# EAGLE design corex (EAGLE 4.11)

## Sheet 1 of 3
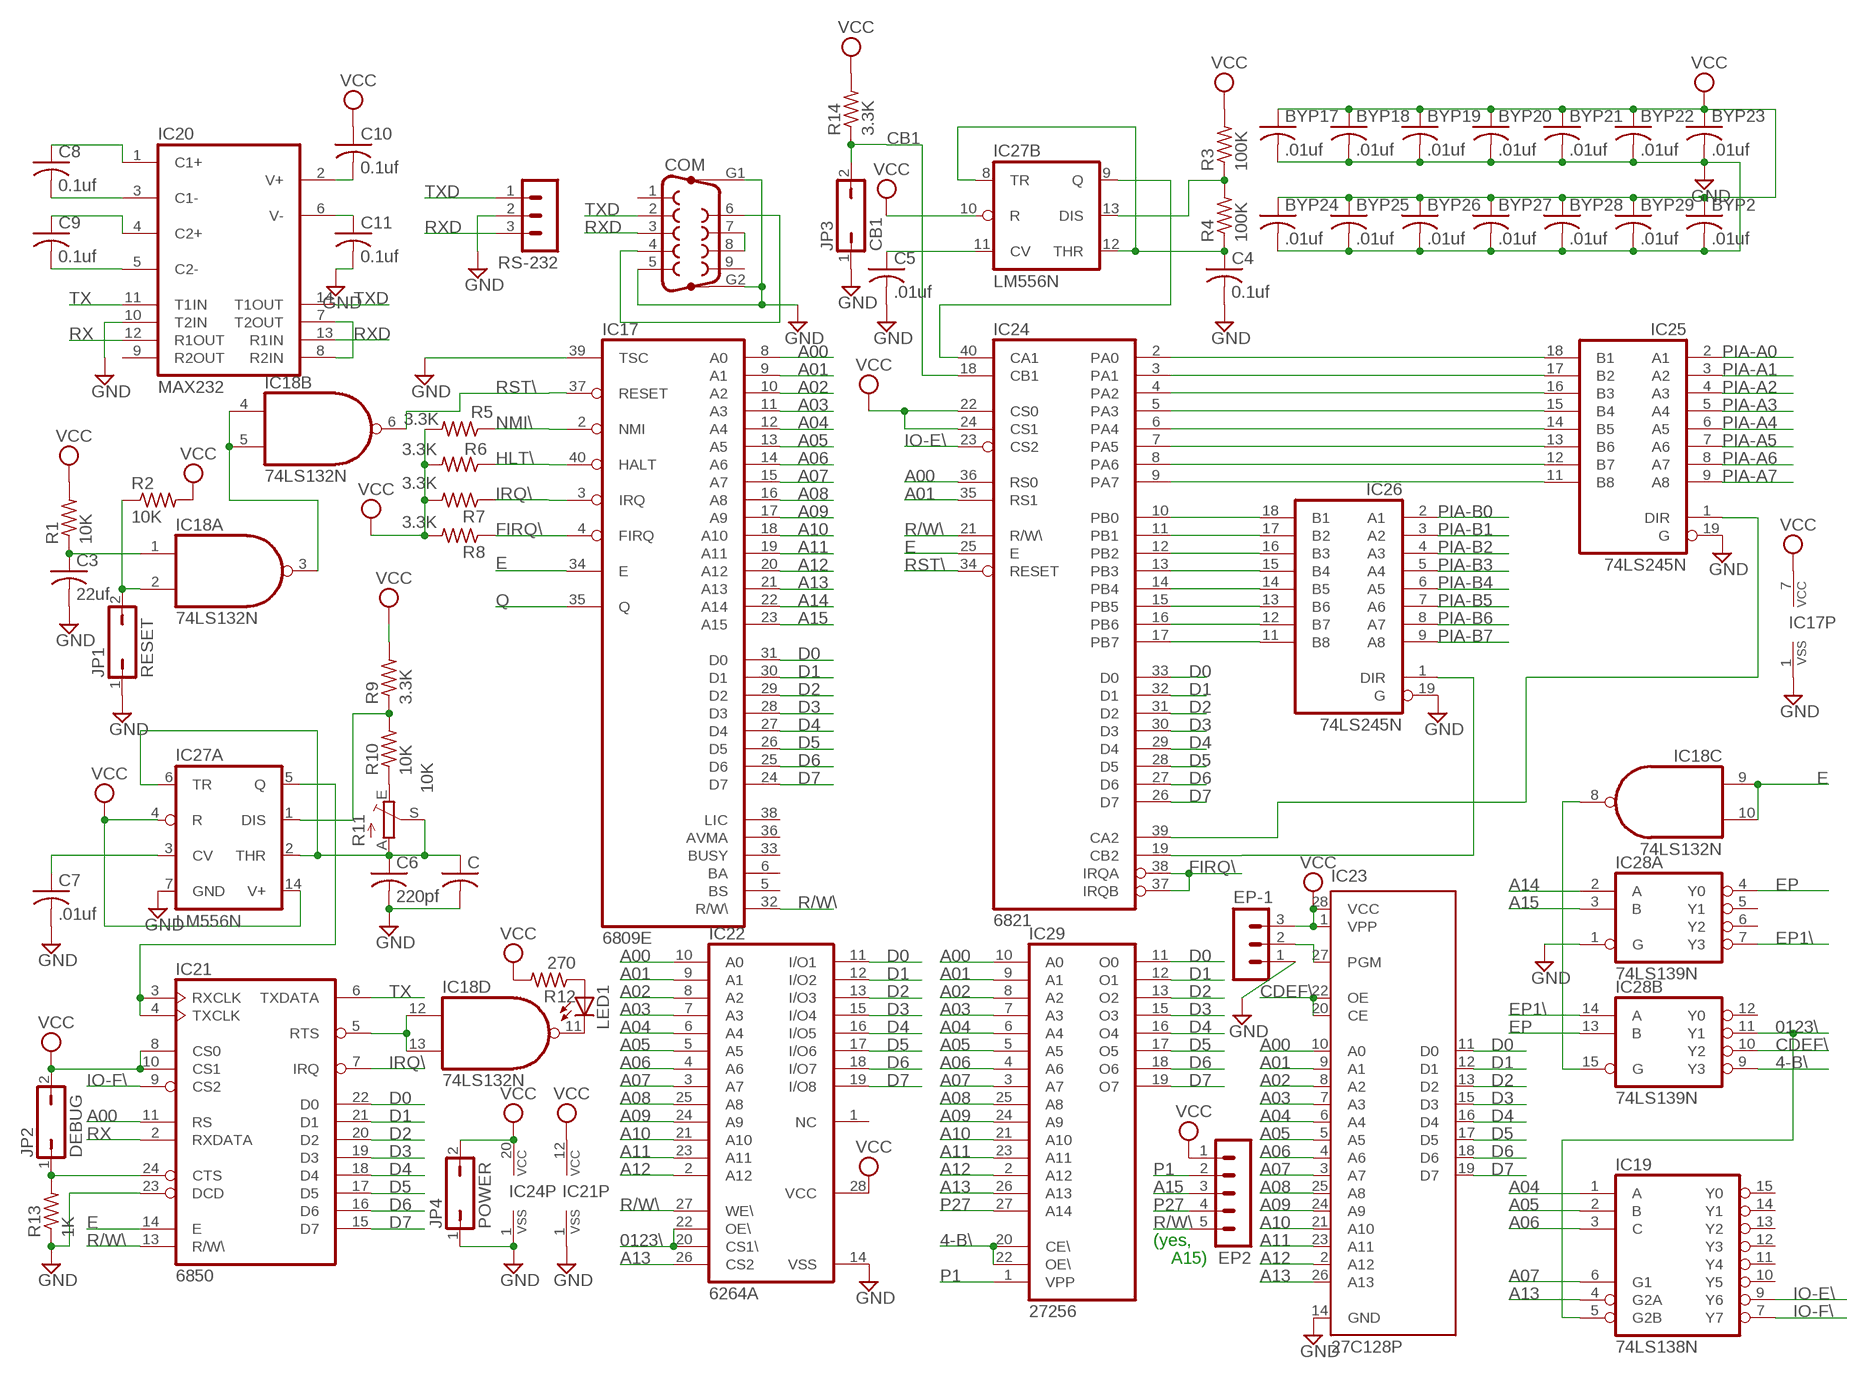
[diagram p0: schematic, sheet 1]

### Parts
BYP2  .01uf  C-US050-025X075  [C050-025X075]
BYP17  .01uf  C-US050-025X075  [C050-025X075]
BYP18  .01uf  C-US050-025X075  [C050-025X075]
BYP19  .01uf  C-US050-025X075  [C050-025X075]
BYP20  .01uf  C-US050-025X075  [C050-025X075]
BYP21  .01uf  C-US050-025X075  [C050-025X075]
BYP22  .01uf  C-US050-025X075  [C050-025X075]
BYP23  .01uf  C-US050-025X075  [C050-025X075]
BYP24  .01uf  C-US050-025X075  [C050-025X075]
BYP25  .01uf  C-US050-025X075  [C050-025X075]
BYP26  .01uf  C-US050-025X075  [C050-025X075]
BYP27  .01uf  C-US050-025X075  [C050-025X075]
BYP28  .01uf  C-US050-025X075  [C050-025X075]
BYP29  .01uf  C-US050-025X075  [C050-025X075]
C  C-US050-025X075  [C050-025X075]
C3  22uf  C-US102-054X133  [C102-054X133]
C4  0.1uf  C-US050-025X075  [C050-025X075]
C5  .01uf  C-US050-025X075  [C050-025X075]
C6  220pf  C-US050-025X075  [C050-025X075]
C7  .01uf  C-US050-025X075  [C050-025X075]
C8  0.1uf  C-US050-025X075  [C050-025X075]
C9  0.1uf  C-US050-025X075  [C050-025X075]
C10  0.1uf  C-US050-025X075  [C050-025X075]
C11  0.1uf  C-US050-025X075  [C050-025X075]
COM  F09HP  [F09HP]
EP2  MA05-1  [MA05-1]
EP-1  MA03-1  [MA03-1]
IC17  6809E  [DIL40]
IC18  74LS132N  74LS00N  [DIL14]
IC19  74LS138N  [DIL16]
IC20  MAX232  [DIL16]
IC21  6850  [DIL24]
IC22  6264A  [DIL28-6]
IC23  27C128P  [DIL28-6]
IC24  6821  [DIL40]
IC25  74LS245N  [DIL20]
IC26  74LS245N  [DIL20]
IC27  LM556N  [DIL14]
IC28  74LS139N  [DIL16]
IC29  27256  [DIL28]
JP1  RESET  JP1Q  [JP1]
JP2  DEBUG  JP1Q  [JP1]
JP3  CB1  JP1Q  [JP1]
JP4  POWER  JP1Q  [JP1]
LED1  LED3MM  [LED3MM]
R1  10K  R-US_0207/7  [0207/7]
R2  10K  R-US_0207/7  [0207/7]
R3  100K  R-US_0207/7  [0207/7]
R4  100K  R-US_0207/7  [0207/7]
R5  3.3K  R-US_0207/7  [0207/7]
R6  3.3K  R-US_0207/7  [0207/7]
R7  3.3K  R-US_0207/7  [0207/7]
R8  3.3K  R-US_0207/7  [0207/7]
R9  3.3K  R-US_0207/7  [0207/7]
R10  10K  R-US_0207/7  [0207/7]
R11  10K  TRIM_EU-B90P  [SP19L]
R12  270  R-US_0207/7  [0207/7]
R13  1K  R-US_0207/7  [0207/7]
R14  3.3K  R-US_0207/7  [0207/7]
RS-232  MA03-1  [MA03-1]

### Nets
4-B\: IC28.9(B:Y3) IC29.20(CE\) IC29.22(OE\)
0123\: IC19.5(G2B) IC22.20(CS1\) IC22.22(OE\) IC28.11(B:Y1)
A00: IC17.8(A0) IC21.11(RS) IC22.10(A0) IC23.10(A0) IC24.36(RS0) IC29.10(A0)
A01: IC17.9(A1) IC22.9(A1) IC23.9(A1) IC24.35(RS1) IC29.9(A1)
A02: IC17.10(A2) IC22.8(A2) IC23.8(A2) IC29.8(A2)
A03: IC17.11(A3) IC22.7(A3) IC23.7(A3) IC29.7(A3)
A04: IC17.12(A4) IC19.1(A) IC22.6(A4) IC23.6(A4) IC29.6(A4)
A05: IC17.13(A5) IC19.2(B) IC22.5(A5) IC23.5(A5) IC29.5(A5)
A06: IC17.14(A6) IC19.3(C) IC22.4(A6) IC23.4(A6) IC29.4(A6)
A07: IC17.15(A7) IC19.6(G1) IC22.3(A7) IC23.3(A7) IC29.3(A7)
A08: IC17.16(A8) IC22.25(A8) IC23.25(A8) IC29.25(A8)
A09: IC17.17(A9) IC22.24(A9) IC23.24(A9) IC29.24(A9)
A10: IC17.18(A10) IC22.21(A10) IC23.21(A10) IC29.21(A10)
A11: IC17.19(A11) IC22.23(A11) IC23.23(A11) IC29.23(A11)
A12: IC17.20(A12) IC22.2(A12) IC23.2(A12) IC29.2(A12)
A13: IC17.21(A13) IC19.4(G2A) IC22.26(CS2) IC23.26(A13) IC29.26(A13)
A14: IC17.22(A14) IC28.2(A:A)
A15: EP2.3 IC17.23(A15) IC28.3(A:B)
CB1: IC24.18(CB1) JP3.2 R14.1
CDEF\: IC23.20(CE) IC23.22(OE) IC28.10(B:Y2)
D0: IC17.31(D0) IC21.22(D0) IC22.11(I/O1) IC23.11(D0) IC24.33(D0) IC29.11(O0)
D1: IC17.30(D1) IC21.21(D1) IC22.12(I/O2) IC23.12(D1) IC24.32(D1) IC29.12(O1)
D2: IC17.29(D2) IC21.20(D2) IC22.13(I/O3) IC23.13(D2) IC24.31(D2) IC29.13(O2)
D3: IC17.28(D3) IC21.19(D3) IC22.15(I/O4) IC23.15(D3) IC24.30(D3) IC29.15(O3)
D4: IC17.27(D4) IC21.18(D4) IC22.16(I/O5) IC23.16(D4) IC24.29(D4) IC29.16(O4)
D5: IC17.26(D5) IC21.17(D5) IC22.17(I/O6) IC23.17(D5) IC24.28(D5) IC29.17(O5)
D6: IC17.25(D6) IC21.16(D6) IC22.18(I/O7) IC23.18(D6) IC24.27(D6) IC29.18(O6)
D7: IC17.24(D7) IC21.15(D7) IC22.19(I/O8) IC23.19(D7) IC24.26(D7) IC29.19(O7)
E: IC17.34(E) IC18.9(C:I0) IC18.10(C:I1) IC21.14(E) IC24.25(E) ; also sheet 3
EP: IC28.4(A:Y0) IC28.13(B:B)
EP1\: IC28.7(A:Y3) IC28.14(B:A)
FIRQ\: IC17.4(FIRQ) IC24.37(IRQB) IC24.38(IRQA) R8.1
GND [Power]: BYP2.2 BYP17.2 BYP18.2 BYP19.2 BYP20.2 BYP21.2 BYP22.2 BYP23.2 BYP24.2 BYP25.2 BYP26.2 BYP27.2 BYP28.2 BYP29.2 C3.2 C4.2 C5.2 C6.2 C7.2 C11.2 C.2 COM.5 COM.G1 COM.G2 EP-1.1 IC17.1(VSS) IC17.39(TSC) IC20.10(T2IN) IC21.1(VSS) IC21.23(DCD) IC22.14(VSS) IC23.14(GND) IC24.1(VSS) IC25.19(G) IC26.19(G) IC27.7(A:GND) IC28.1(A:G) JP1.1 JP3.1 JP4.1 R13.1 RS-232.2 ; also sheet 2,3
HLT\: IC17.40(HALT) R5.1
IO-E\: IC19.9(Y6) IC24.23(CS2)
IO-F\: IC19.7(Y7) IC21.9(CS2)
IRQ\: IC17.3(IRQ) IC21.7(IRQ) R7.1
N$1: COM.4 COM.6
N$4: EP-1.2 IC23.27(PGM)
N$5: IC24.2(PA0) IC25.18(B1)
N$6: IC18.3(A:O) IC18.4(B:I0) IC18.5(B:I1)
N$21: C3.1 IC18.1(A:I0) R1.1
N$22: IC18.2(A:I1) JP1.2 R2.1
N$23: IC21.3(RXCLK) IC21.4(TXCLK) IC27.5(A:Q)
N$24: IC24.10(PB0) IC26.18(B1)
N$25: IC24.11(PB1) IC26.17(B2)
N$27: C6.1 C.1 IC27.2(A:THR) IC27.6(A:TR) R11.A R11.S
N$28: IC27.1(A:DIS) R9.1 R10.2
N$94: IC24.12(PB2) IC26.16(B3)
N$124: IC24.13(PB3) IC26.15(B4)
N$125: IC24.14(PB4) IC26.14(B5)
N$126: IC24.15(PB5) IC26.13(B6)
N$127: IC24.16(PB6) IC26.12(B7)
N$128: IC24.17(PB7) IC26.11(B8)
N$129: IC24.3(PA1) IC25.17(B2)
N$130: IC24.4(PA2) IC25.16(B3)
N$131: IC24.5(PA3) IC25.15(B4)
N$132: IC24.6(PA4) IC25.14(B5)
N$133: IC24.7(PA5) IC25.13(B6)
N$134: IC24.8(PA6) IC25.12(B7)
N$135: IC24.9(PA7) IC25.11(B8)
N$136: IC24.19(CB2) IC26.1(DIR)
N$137: IC24.39(CA2) IC25.1(DIR)
N$138: IC24.40(CA1) IC27.9(B:Q)
N$140: C4.1 IC27.8(B:TR) IC27.12(B:THR) R4.1
N$141: IC27.13(B:DIS) R3.1 R4.2
N$142: C5.1 IC27.11(B:CV)
N$143: R10.1 R11.E
N$145: COM.7 COM.8
N$147: IC18.12(D:I0) IC18.13(D:I1) IC21.5(RTS)
N$148: IC18.11(D:O) LED1.K(C)
N$149: LED1.A R12.1
N$150: IC21.24(CTS) JP2.1 R13.2
N$151: IC18.8(C:O) IC28.15(B:G)
N$153: IC20.7(T2OUT) IC20.8(R2IN)
N$154: C7.1 IC27.3(A:CV)
N$155: C9.2 IC20.5(C2-)
N$156: C9.1 IC20.4(C2+)
N$157: C8.2 IC20.3(C1-)
N$158: C8.1 IC20.1(C1+)
N$159: C11.1 IC20.6(V-)
N$160: C10.2 IC20.2(V+)
NMI\: IC17.2(NMI) R6.1
P1: EP2.2 IC29.1(VPP)
P27: EP2.4 IC29.27(A14)
PIA-A0: IC25.2(A1) ; also sheet 2
PIA-A1: IC25.3(A2) ; also sheet 2
PIA-A2: IC25.4(A3) ; also sheet 2
PIA-A3: IC25.5(A4) ; also sheet 2
PIA-A4: IC25.6(A5) ; also sheet 2
PIA-A5: IC25.7(A6) ; also sheet 2
PIA-A6: IC25.8(A7) ; also sheet 2
PIA-A7: IC25.9(A8) ; also sheet 2
PIA-B0: IC26.2(A1) ; also sheet 2
PIA-B1: IC26.3(A2) ; also sheet 2
PIA-B2: IC26.4(A3) ; also sheet 2
PIA-B3: IC26.5(A4) ; also sheet 2
PIA-B4: IC26.6(A5) ; also sheet 2
PIA-B5: IC26.7(A6) ; also sheet 2
PIA-B6: IC26.8(A7) ; also sheet 2
PIA-B7: IC26.9(A8) ; also sheet 2
Q: IC17.35(Q) ; also sheet 3
R/W\: EP2.5 IC17.32(R/W\) IC21.13(R/W\) IC22.27(WE\) IC24.21(R/W\)
RST\: IC17.37(RESET) IC18.6(B:O) IC24.34(RESET)
RX: IC20.12(R1OUT) IC21.2(RXDATA)
RXD: COM.3 IC20.13(R1IN) RS-232.3
TX: IC20.11(T1IN) IC21.6(TXDATA)
TXD: COM.2 IC20.14(T1OUT) RS-232.1
VCC [Power]: BYP2.1 BYP17.1 BYP18.1 BYP19.1 BYP20.1 BYP21.1 BYP22.1 BYP23.1 BYP24.1 BYP25.1 BYP26.1 BYP27.1 BYP28.1 BYP29.1 C10.1 EP2.1 EP-1.3 IC17.7(VCC) IC21.8(CS0) IC21.10(CS1) IC21.12(VCC) IC22.28(VCC) IC23.1(VPP) IC23.28(VCC) IC24.20(VCC) IC24.22(CS0) IC24.24(CS1) IC27.4(A:R) IC27.10(B:R) IC27.14(A:V+) JP2.2 JP4.2 R1.2 R2.2 R3.2 R5.2 R6.2 R7.2 R8.2 R9.2 R12.2 R14.2 ; also sheet 2,3
Unconnected: COM.1 COM.9 IC17.5(BS) IC17.6(BA) IC17.33(BUSY) IC17.36(AVMA) IC17.38(LIC) IC19.10(Y5) IC19.11(Y4) IC19.12(Y3) IC19.13(Y2) IC19.14(Y1) IC19.15(Y0) IC20.9(R2OUT) IC22.1(NC) IC28.5(A:Y1) IC28.6(A:Y2) IC28.12(B:Y0)

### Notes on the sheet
- (yes,
- A15)

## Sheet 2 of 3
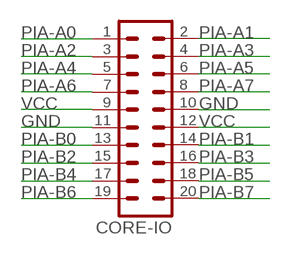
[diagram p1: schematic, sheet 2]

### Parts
CORE-IO  MA10-2  [MA10-2]

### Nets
GND [Power]: CORE-IO.10 CORE-IO.11 ; also sheet 1,3
PIA-A0: CORE-IO.1 ; also sheet 1
PIA-A1: CORE-IO.2 ; also sheet 1
PIA-A2: CORE-IO.3 ; also sheet 1
PIA-A3: CORE-IO.4 ; also sheet 1
PIA-A4: CORE-IO.5 ; also sheet 1
PIA-A5: CORE-IO.6 ; also sheet 1
PIA-A6: CORE-IO.7 ; also sheet 1
PIA-A7: CORE-IO.8 ; also sheet 1
PIA-B0: CORE-IO.13 ; also sheet 1
PIA-B1: CORE-IO.14 ; also sheet 1
PIA-B2: CORE-IO.15 ; also sheet 1
PIA-B3: CORE-IO.16 ; also sheet 1
PIA-B4: CORE-IO.17 ; also sheet 1
PIA-B5: CORE-IO.18 ; also sheet 1
PIA-B6: CORE-IO.19 ; also sheet 1
PIA-B7: CORE-IO.20 ; also sheet 1
VCC [Power]: CORE-IO.9 CORE-IO.12 ; also sheet 1,3

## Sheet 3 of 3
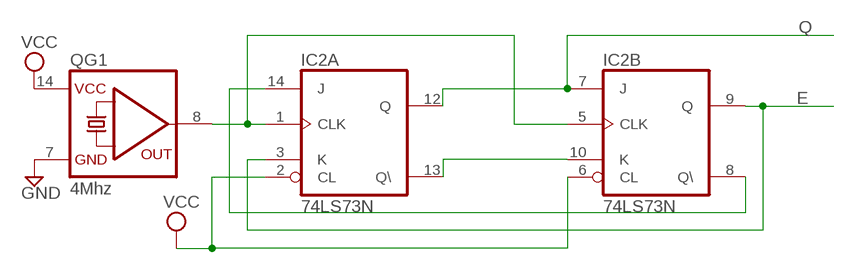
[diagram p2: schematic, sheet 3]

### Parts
IC2  74LS73N  [DIL14]
QG1  4Mhz  QG5860  [DIL14S]

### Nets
E: IC2.3(A:K) IC2.9(B:Q) ; also sheet 1
GND [Power]: QG1.7(GND) ; also sheet 1,2
N$2: IC2.1(A:CLK) IC2.5(B:CLK) QG1.8(OUT)
N$3: IC2.10(B:K) IC2.13(A:Q\)
N$7: IC2.8(B:Q\) IC2.14(A:J)
Q: IC2.7(B:J) IC2.12(A:Q) ; also sheet 1
VCC [Power]: IC2.2(A:CL) IC2.6(B:CL) QG1.14(VCC) ; also sheet 1,2

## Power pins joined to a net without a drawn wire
GND: IC2.11(P:GND) IC18.7(P:GND) IC19.8(GND) IC20.15(GND) IC25.10(GND) IC26.10(GND) IC28.8(P:GND) IC29.14(GND)
VCC: IC2.4(P:VCC) IC18.14(P:VCC) IC19.16(VCC) IC20.16(VCC) IC25.20(VCC) IC26.20(VCC) IC28.16(P:VCC) IC29.28(VCC)

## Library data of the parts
BYP2 BYP17-BYP29 C C3-C11 = rcl:C-US: CAPACITOR, American symbol
COM = con-subd:F09HP: SUB-D
CORE-IO = con-lstb:MA10-2: PIN HEADER
EP2 = con-lstb:MA05-1: PIN HEADER
EP-1 RS-232 = con-lstb:MA03-1: PIN HEADER
IC2 = 74xx-us:74*73: Dual J-K FLIP FLOP, clear
IC17 = micro-motorola:6809E: MICROCONTROLLER/MEMORY DEVICE
IC18 = 74xx-us:74*00: Quad 2-input NAND gate
IC19 = 74xx-us:74*138: 3-line to 8-line DECODER/DEMULTIPLEXER
IC20 = maxim:MAX232: RS232 TRANSEIVER
IC21 = micro-motorola:6850: MICROCONTROLLER/MEMORY DEVICE
IC22 = memory-hitachi:6264A: MEMORY
IC23 = microchip:27*128: CMOS EPROM 128 K (16 K x 8)
IC24 = micro-motorola:6821: MICROCONTROLLER/MEMORY DEVICE
IC25 IC26 = 74xx-us:74*245: Octal BUS TRANSCEIVER, 3-state
IC27 = linear:*556: Dual TIMER
IC28 = 74xx-us:74*139: Dual 2-line to 4-line DECODER/DEMULTIPLEXER
IC29 = memory:27256: MEMORY
JP1-JP4 = jumper:JP1Q: JUMPER
LED1 = led:LED: LED
QG1 = crystal:QG5860: CRYSTAL RESONATOR
R1-R10 R12-R14 = rcl:R-US_: RESISTOR, American symbol
R11 = pot:TRIM_EU-: POTENTIOMETER

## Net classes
1 Power: width 0.508 mm, drill 0.254 mm, clearance 0.254 mm

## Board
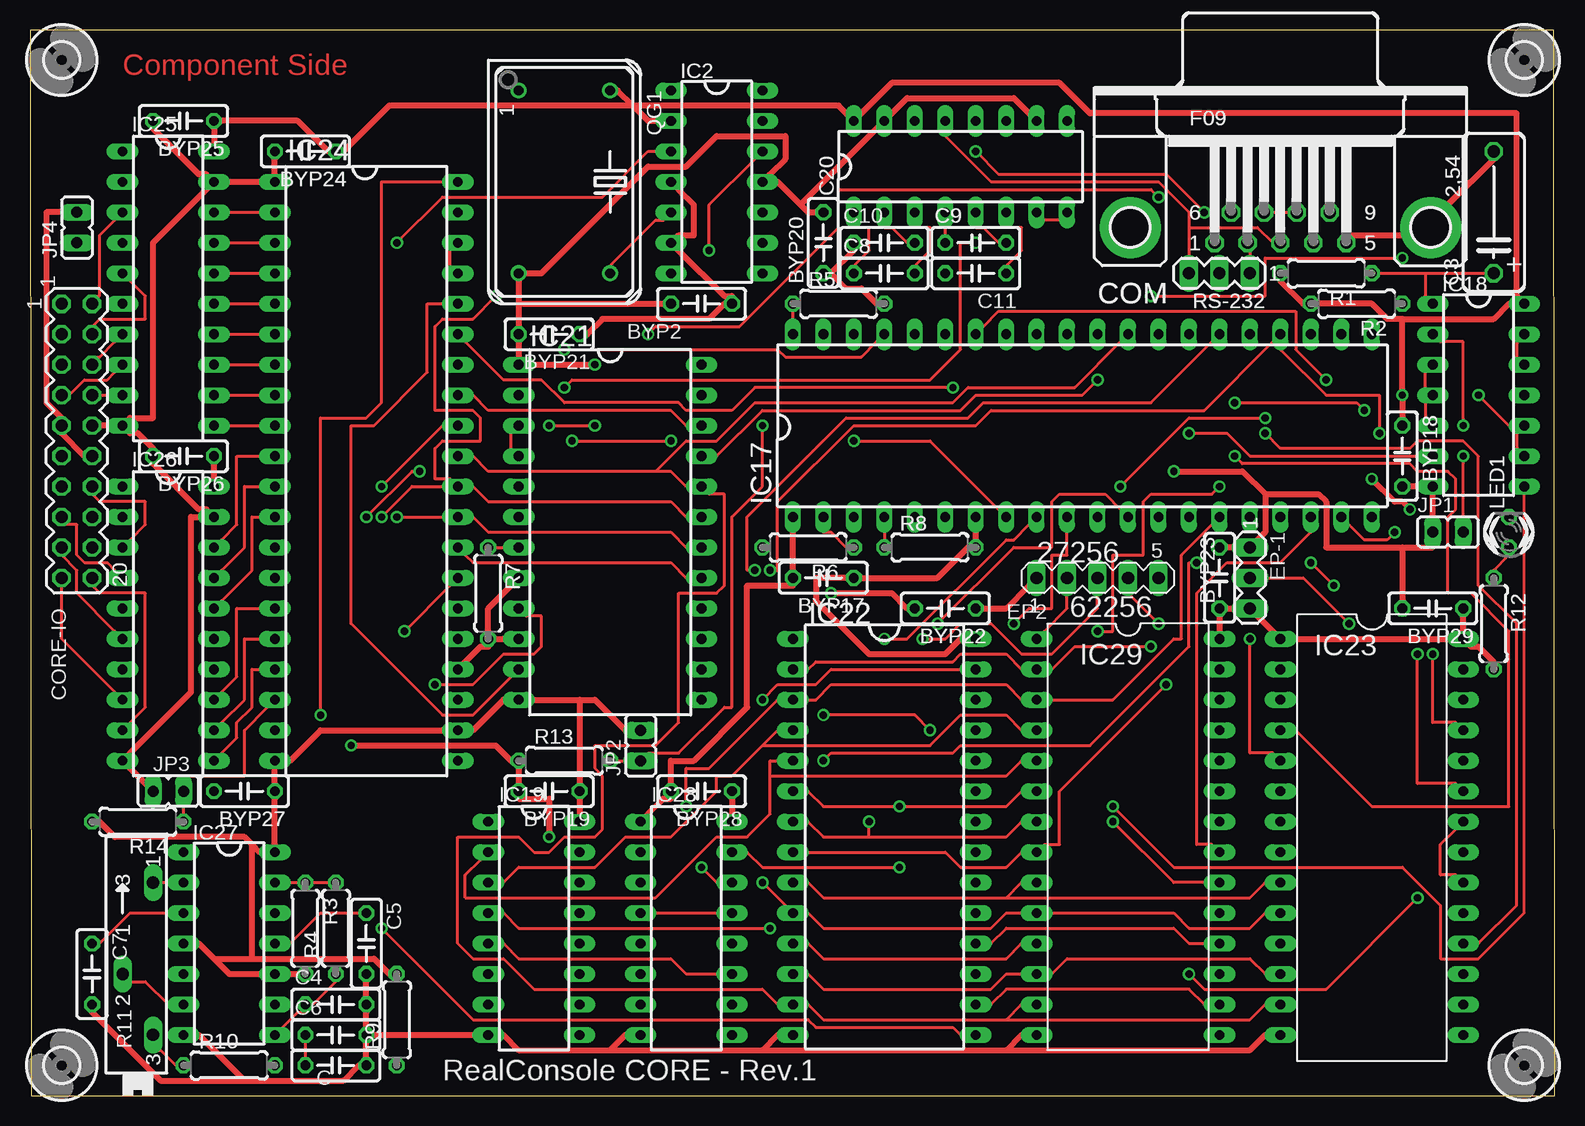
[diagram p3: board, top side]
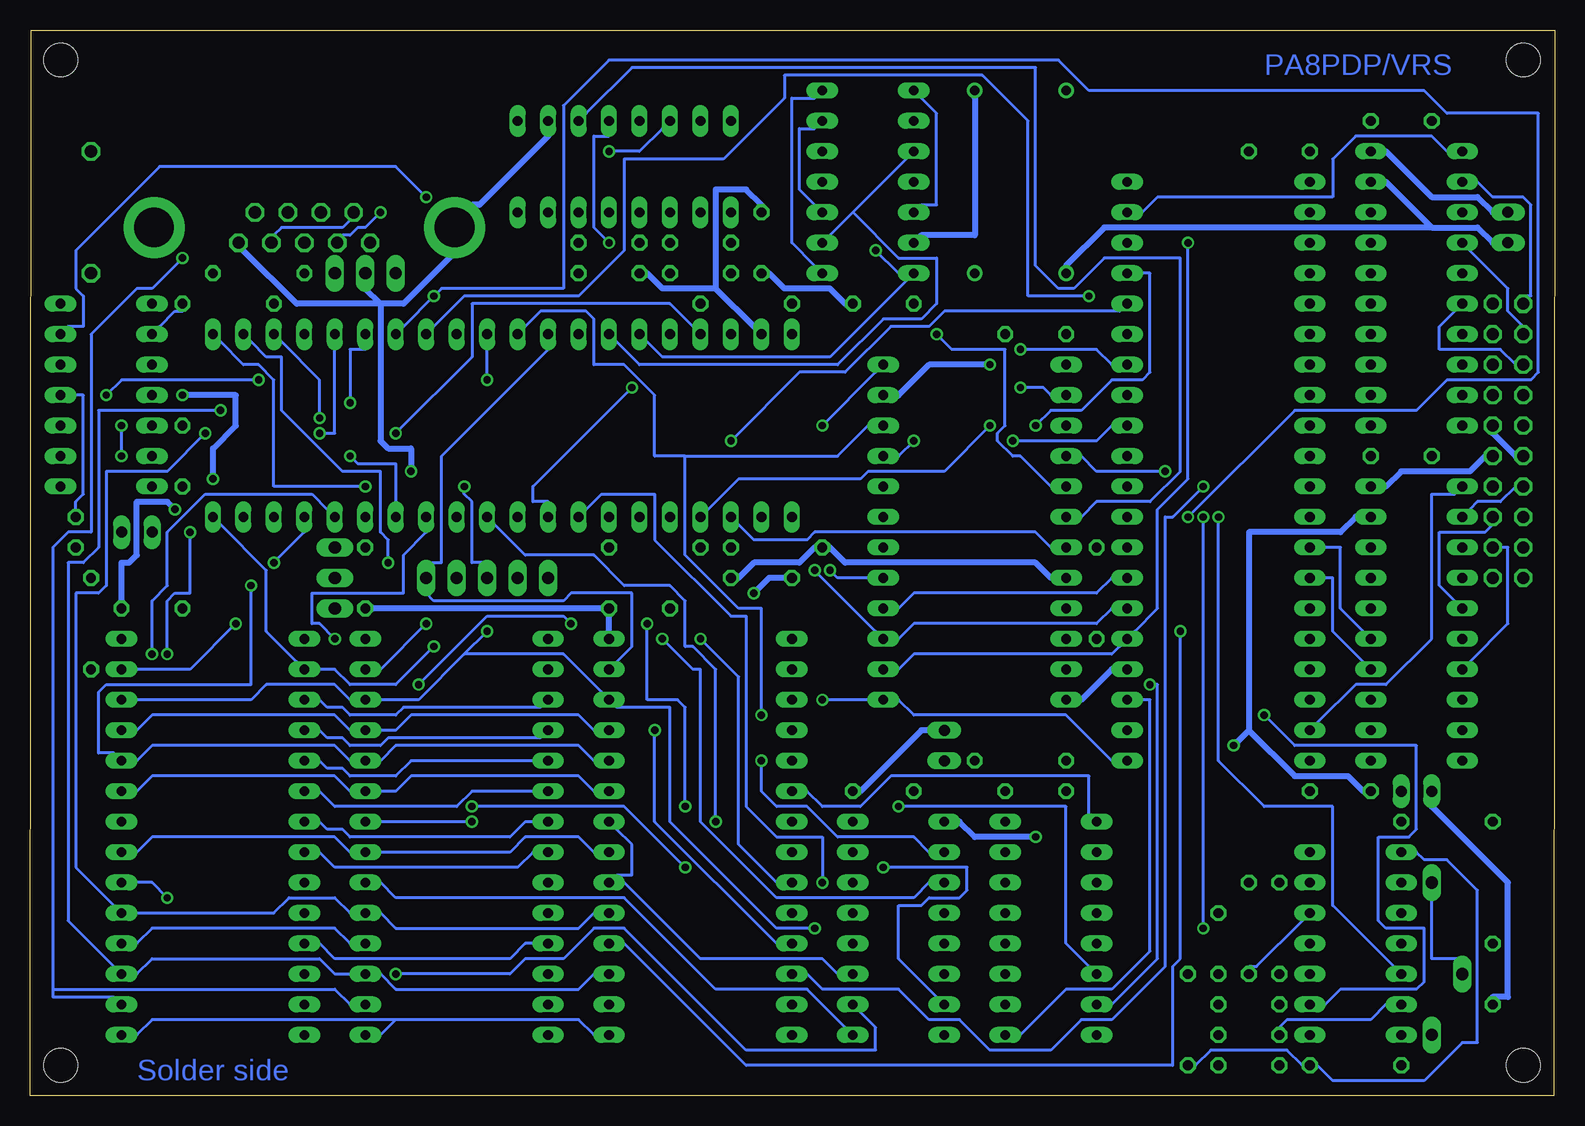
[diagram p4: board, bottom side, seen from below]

Size 127.11 x 88.87 mm. Coordinates in mm from the lower left corner, seen from the top.
Outline: 0.1,0 127.11,0 127.01,88.87 0,88.87 0.1,0
Copper layers (1*16): Top 0.035mm / dielectric 1.5mm / Bottom 0.035mm
Design rules "olimex10mil": minimum track width 10mil, minimum drill 24mil, track to track 10mil, track to pad 10mil, pad to pad 10mil, via to via 10mil, smd to smd 10mil, copper to edge 40mil, drill to drill 10mil, minimum pad ring 10mil, minimum via ring 8mil, stop-mask expansion 0mil, vias tented up to drill 0mil, thermal gap 10mil

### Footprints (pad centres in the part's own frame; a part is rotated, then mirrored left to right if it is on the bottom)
C050-025X075 = drill 0.813 octagon: 1 -2.54,0; 2 2.54,0
C102-054X133 = drill 1.016 octagon: 1 -5.08,0; 2 5.08,0
F09HP = drill 1.016 octagon: 1 -5.486,-1.27; 2 -2.743,-1.27; 3 0,-1.27; 4 2.743,-1.27; 5 5.486,-1.27; 6 -4.115,1.27; 7 -1.372,1.27; 8 1.372,1.27; 9 4.115,1.27 | drill 3.302 pad 5.08 round: G1 -12.522,0; G2 12.522,0
MA10-2 = drill 1.016 octagon: 1 -11.43,-1.27; 2 -11.43,1.27; 3 -8.89,-1.27; 4 -8.89,1.27; 5 -6.35,-1.27; 6 -6.35,1.27; 7 -3.81,-1.27; 8 -3.81,1.27; 9 -1.27,-1.27; 10 -1.27,1.27; 11 1.27,-1.27; 12 1.27,1.27; 13 3.81,-1.27; 14 3.81,1.27; 15 6.35,-1.27; 16 6.35,1.27; 17 8.89,-1.27; 18 8.89,1.27; 19 11.43,-1.27; 20 11.43,1.27
MA05-1 = drill 1.016 long: 1 -5.08,0; 2 -2.54,0; 3 0,0; 4 2.54,0; 5 5.08,0
MA03-1 = drill 1.016 long: 1 -2.54,0; 2 0,0; 3 2.54,0
DIL14 = drill 0.813 long: 1 -7.62,-3.81; 2 -5.08,-3.81; 3 -2.54,-3.81; 4 0,-3.81; 5 2.54,-3.81; 6 5.08,-3.81; 7 7.62,-3.81; 8 7.62,3.81; 9 5.08,3.81; 10 2.54,3.81; 11 0,3.81; 12 -2.54,3.81; 13 -5.08,3.81; 14 -7.62,3.81
DIL40 = drill 0.813 long: 1 -24.13,-7.62; 2 -21.59,-7.62; 3 -19.05,-7.62; 4 -16.51,-7.62; 5 -13.97,-7.62; 6 -11.43,-7.62; 7 -8.89,-7.62; 8 -6.35,-7.62; 9 -3.81,-7.62; 10 -1.27,-7.62; 11 1.27,-7.62; 12 3.81,-7.62; 13 6.35,-7.62; 14 8.89,-7.62; 15 11.43,-7.62; 16 13.97,-7.62; 17 16.51,-7.62; 18 19.05,-7.62; 19 21.59,-7.62; 20 24.13,-7.62; 21 24.13,7.62; 22 21.59,7.62; 23 19.05,7.62; 24 16.51,7.62; 25 13.97,7.62; 26 11.43,7.62; 27 8.89,7.62; 28 6.35,7.62; 29 3.81,7.62; 30 1.27,7.62; 31 -1.27,7.62; 32 -3.81,7.62; 33 -6.35,7.62; 34 -8.89,7.62; 35 -11.43,7.62; 36 -13.97,7.62; 37 -16.51,7.62; 38 -19.05,7.62; 39 -21.59,7.62; 40 -24.13,7.62
DIL16 = drill 0.813 long: 1 -8.89,-3.81; 2 -6.35,-3.81; 3 -3.81,-3.81; 4 -1.27,-3.81; 5 1.27,-3.81; 6 3.81,-3.81; 7 6.35,-3.81; 8 8.89,-3.81; 9 8.89,3.81; 10 6.35,3.81; 11 3.81,3.81; 12 1.27,3.81; 13 -1.27,3.81; 14 -3.81,3.81; 15 -6.35,3.81; 16 -8.89,3.81
DIL24 = drill 0.813 long: 1 -13.97,-7.62; 2 -11.43,-7.62; 3 -8.89,-7.62; 4 -6.35,-7.62; 5 -3.81,-7.62; 6 -1.27,-7.62; 7 1.27,-7.62; 8 3.81,-7.62; 9 6.35,-7.62; 10 8.89,-7.62; 11 11.43,-7.62; 12 13.97,-7.62; 13 13.97,7.62; 14 11.43,7.62; 15 8.89,7.62; 16 6.35,7.62; 17 3.81,7.62; 18 1.27,7.62; 19 -1.27,7.62; 20 -3.81,7.62; 21 -6.35,7.62; 22 -8.89,7.62; 23 -11.43,7.62; 24 -13.97,7.62
DIL28-6 = drill 0.813 long: 1 -16.51,-7.62; 2 -13.97,-7.62; 3 -11.43,-7.62; 4 -8.89,-7.62; 5 -6.35,-7.62; 6 -3.81,-7.62; 7 -1.27,-7.62; 8 1.27,-7.62; 9 3.81,-7.62; 10 6.35,-7.62; 11 8.89,-7.62; 12 11.43,-7.62; 13 13.97,-7.62; 14 16.51,-7.62; 15 16.51,7.62; 16 13.97,7.62; 17 11.43,7.62; 18 8.89,7.62; 19 6.35,7.62; 20 3.81,7.62; 21 1.27,7.62; 22 -1.27,7.62; 23 -3.81,7.62; 24 -6.35,7.62; 25 -8.89,7.62; 26 -11.43,7.62; 27 -13.97,7.62; 28 -16.51,7.62
DIL20 = drill 0.813 long: 1 -11.43,-3.81; 2 -8.89,-3.81; 3 -6.35,-3.81; 4 -3.81,-3.81; 5 -1.27,-3.81; 6 1.27,-3.81; 7 3.81,-3.81; 8 6.35,-3.81; 9 8.89,-3.81; 10 11.43,-3.81; 11 11.43,3.81; 12 8.89,3.81; 13 6.35,3.81; 14 3.81,3.81; 15 1.27,3.81; 16 -1.27,3.81; 17 -3.81,3.81; 18 -6.35,3.81; 19 -8.89,3.81; 20 -11.43,3.81
DIL28 = drill 0.813 long: 1 -16.51,-7.62; 2 -13.97,-7.62; 3 -11.43,-7.62; 4 -8.89,-7.62; 5 -6.35,-7.62; 6 -3.81,-7.62; 7 -1.27,-7.62; 8 1.27,-7.62; 9 3.81,-7.62; 10 6.35,-7.62; 11 8.89,-7.62; 12 11.43,-7.62; 13 13.97,-7.62; 14 16.51,-7.62; 15 16.51,7.62; 16 13.97,7.62; 17 11.43,7.62; 18 8.89,7.62; 19 6.35,7.62; 20 3.81,7.62; 21 1.27,7.62; 22 -1.27,7.62; 23 -3.81,7.62; 24 -6.35,7.62; 25 -8.89,7.62; 26 -11.43,7.62; 27 -13.97,7.62; 28 -16.51,7.62
JP1 = drill 0.914 long: 1 0,-1.27; 2 0,1.27
LED3MM = drill 0.813 octagon: A -1.27,0; K 1.27,0
DIL14S = drill 0.813 round: 1 -7.62,-3.81; 7 7.62,-3.81; 8 7.62,3.81; 14 -7.62,3.81
0207/7 = drill 0.813 octagon: 1 -3.81,0; 2 3.81,0
SP19L = drill 1.016 long: A 5.715,-1.27; E -6.985,-1.27; S -1.905,1.27
2,8 = hole 2.8: 0,0

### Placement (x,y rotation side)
BYP2  55.98,66.05 180 top
BYP17  66.14,43.19 180 top
BYP18  114.4,53.35 270 top
BYP19  43.28,25.41 180 top
BYP20  66.14,71.13 90 top
BYP21  43.28,63.51 180 top
BYP22  76.3,40.65 180 top
BYP23  99.16,43.19 90 top
BYP24  22.96,78.75 180 top
BYP25  12.8,81.29 180 top
BYP26  12.8,53.35 180 top
BYP27  17.88,25.41 180 top
BYP28  55.98,25.41 180 top
BYP29  116.94,40.65 180 top
C  25.5,2.55 0 top
C3  122.02,73.67 90 top
C4  25.5,7.63 0 top
C5  28.04,12.71 270 top
C6  25.5,5.09 0 top
C7  5.18,10.17 270 top
C8  71.22,68.59 0 top
C9  78.84,71.13 0 top
C10  71.22,71.13 0 top
C11  78.84,68.59 180 top
COM  104.24,72.4 0 top
CORE-IO  3.91,54.62 270 top
EP2  89,43.19 0 top
EP-1  101.7,43.19 270 top
IC2  57.25,76.21 270 top
IC17  87.73,55.89 0 top
IC18  120.75,58.43 270 top
IC19  42.01,13.98 270 top
IC20  77.57,77.48 0 top
IC21  48.36,47 270 top
IC22  71.22,21.6 270 top
IC23  111.86,21.6 270 top
IC24  28.04,52.08 270 top
IC25  11.53,67.32 270 top
IC26  11.53,39.38 270 top
IC27  16.61,12.71 270 top
IC28  54.71,13.98 270 top
IC29  91.54,21.6 270 top
JP1  118.21,47 270 top
JP2  50.9,29.22 0 top
JP3  11.53,25.41 270 top
JP4  3.91,72.4 0 top
LED1  123.29,47 90 top
QG1  44.55,76.21 270 top
R1  108.05,68.59 180 top
R2  110.59,66.05 180 top
R3  22.96,13.98 270 top
R4  25.5,13.98 90 top
R5  67.41,66.05 0 top
R6  64.87,45.73 180 top
R7  38.2,41.92 270 top
R8  75.03,45.73 0 top
R9  30.58,6.36 90 top
R10  16.61,2.55 0 top
R11  8.99,12.08 90 top
R12  122.02,39.38 270 top
R13  44.55,27.95 0 top
R14  8.99,22.87 180 top
RS-232  99.16,68.59 180 top
U$3  [2,8]  2.64,86.37 0 top
U$4  [2,8]  2.64,2.55 0 top
U$5  [2,8]  124.56,86.37 0 top
U$6  [2,8]  124.56,2.55 0 top

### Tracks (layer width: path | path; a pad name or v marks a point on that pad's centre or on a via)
4-B\  (via drill 0.61)
  Top 0.254: v90.27,22.87 95.35,17.79 97.89,17.79 IC29.20
  Bottom 0.254: IC28.9 59.15,5.73 62.33,8.9 69.95,8.9 77.57,16.52 96.62,16.52 97.89,17.79 IC29.20 | v90.27,22.87 97.89,22.87 IC29.22
0123\
  Top 0.254: IC19.5 39.47,12.71 40.74,11.44 53.44,11.44 54.71,10.17 57.25,10.17 IC28.11
  Bottom 0.254: IC28.11 59.79,10.17 61.06,11.44 71.22,11.44 77.57,17.79 IC22.20 78.2,18.43 76.93,18.43 76.93,20.97 78.2,22.24 IC22.22
A00  (via drill 0.61)
  Top 0.254: IC23.10 102.97,15.25 101.7,13.98 96.62,13.98 95.35,15.25 85.19,15.25 IC29.10 82.65,15.25 81.38,15.25 80.11,13.98 66.14,13.98 64.87,15.25 IC22.10 62.96,15.89 v61.06,17.79 | IC21.11 40.1,34.94 36.93,31.76 34.39,31.76 26.77,39.38 26.77,55.89 28.67,55.89 33.12,60.34 33.12,66.05 34.39,66.05 IC24.36 | v68.68,54.62 75.03,54.62 80.74,48.91 IC17.8
  Bottom 0.254: v68.68,54.62 62.96,60.34 59.15,60.34 55.34,64.15 52.17,64.15 50.9,65.42 36.29,65.42 IC24.36 | v61.06,17.79 61.06,21.6 64.87,21.6 67.41,24.14 67.41,40.02 68.68,40.02 75.03,46.37 75.03,50.18 79.47,50.18 80.74,48.91 IC17.8
A01  (via drill 0.61)
  Top 0.254: 81.38,16.52 66.14,16.52 64.87,17.79 IC22.9 | 81.38,16.52 82.65,17.79 IC29.9 | v71.22,38.11 73.12,38.11 81.38,46.37 82.01,46.37 83.28,47.64 IC17.9 | 81.38,16.52 101.7,16.52 102.97,17.79 IC23.9 | v76.93,59.07 60.42,59.07 58.52,57.16 54.71,57.16 54.07,57.8 44.55,57.8 42.64,59.7 39.47,59.7 36.29,62.88 IC24.35
  Bottom 0.254: v71.22,38.11 68.04,34.94 68.04,20.97 64.87,17.79 IC22.9 | v76.93,59.07 85.19,50.81 85.19,49.54 83.92,49.54 IC17.9
A02  (via drill 0.61)
  Top 0.254: IC22.8 64.87,20.33 76.3,20.33 77.57,19.06 81.38,19.06 82.65,20.33 IC29.8 84.55,20.97 85.82,20.97 85.82,25.41 v94.71,34.3 | v82.01,39.38 83.28,40.65 85.19,40.65 85.19,45.1 86.46,45.1 86.46,47 IC17.10
  Bottom 0.254: IC23.8 102.97,20.33 101.7,19.06 86.46,19.06 85.19,20.33 IC29.8 | v82.01,39.38 82.65,40.02 89,40.02 v94.71,34.3
A03  (via drill 0.61)
  Top 0.254: 69.95,21.6 81.38,21.6 82.65,22.87 IC29.7 | 69.95,21.6 66.14,21.6 64.87,22.87 IC22.7 | 69.95,21.6 v69.95,22.87
  Bottom 0.254: v69.95,22.87 69.95,35.57 71.85,37.48 72.49,37.48 72.49,41.29 73.76,42.56 77.57,42.56 80.11,45.1 85.82,45.1 88.36,47.64 IC17.11 | IC23.7 102.97,22.87 102.33,22.24 101.06,22.24 100.43,21.6 87.09,21.6 85.82,22.87 85.19,22.87 IC29.7
A04  (via drill 0.61)
  Top 0.254: IC29.6 82.65,25.41 81.38,24.14 v72.49,24.14 66.14,24.14 64.87,25.41 IC22.6 | v75.66,39.38 82.01,45.73 85.19,45.73 85.19,49.54 85.82,50.18 89.63,50.18 90.9,48.91 IC17.12
  Bottom 0.254: IC19.1 38.83,23.51 38.83,26.68 55.34,26.68 57.88,24.14 61.06,24.14 62.33,25.41 IC22.6 | v75.66,39.38 75.66,33.03 73.12,33.03 72.49,32.4 v72.49,24.14 | IC23.6 102.97,25.41 101.7,24.14 91.54,24.14 90.27,25.41 85.19,25.41 IC29.6
A05  (via drill 0.61)
  Top 0.254: 61.69,26.68 61.69,27.95 62.33,27.95 IC22.5 | 61.69,26.68 61.69,23.51 59.79,21.6 57.25,21.6 52.17,16.52 36.29,16.52 36.29,18.43 37.56,19.7 IC19.2 | 61.69,26.68 81.38,26.68 82.65,27.95 IC29.5 | v101.7,38.11 101.7,28.59 103.6,28.59 IC23.5
  Bottom 0.254: IC23.5 102.97,27.95 102.33,27.32 101.06,27.32 100.43,26.68 96.62,26.68 95.35,27.95 85.19,27.95 IC29.5 | v101.7,38.11 102.97,39.38 103.6,39.38 103.6,41.92 95.98,41.92 95.98,45.1 94.08,47 IC17.13
A06  (via drill 0.61)
  Top 0.254: v100.43,53.35 101.06,52.72 115.03,52.72 115.67,52.08 118.21,52.08 118.84,51.45 118.84,48.91 118.21,48.27 118.21,41.92 120.11,41.92 123.29,38.75 123.29,24.14 111.86,24.14 105.51,30.49 IC23.4 | 61.06,29.22 62.33,30.49 IC22.4 | 61.06,29.22 58.52,26.68 57.25,26.68 57.25,25.41 53.44,21.6 49.63,21.6 47.09,19.06 40.74,19.06 39.47,17.79 IC19.3 | 61.06,29.22 75.03,29.22 77.57,31.76 81.38,31.76 82.65,30.49 IC29.4
  Bottom 0.254: v100.43,53.35 99.79,52.72 96.62,52.72 96.62,49.54 IC17.14 | IC23.4 102.97,30.49 102.33,29.86 101.06,29.86 100.43,29.22 97.89,29.22 97.25,29.86 84.55,29.86 IC29.4
A07  (via drill 0.61)
  Top 0.254: v54.71,24.14 54.71,27.32 56.61,27.32 62.33,33.03 IC22.3 64.87,33.03 65.5,33.03 66.77,34.3 81.38,34.3 82.65,33.03 IC29.3 85.19,33.03 90.27,33.03 95.35,38.11 95.98,38.11 95.98,45.1 98.52,47.64 IC17.15
  Bottom 0.254: v54.71,24.14 40.74,24.14 40.74,12.71 38.83,10.81 IC19.6 | IC23.3 102.97,33.03 102.33,32.4 101.06,32.4 100.43,31.76 96.62,31.76 95.98,32.4 84.55,32.4 IC29.3
A08  (via drill 0.61)
  Top 0.254: v116.94,36.84 116.94,31.13 118.84,31.13 IC23.25
  Bottom 0.254: IC22.25 80.11,30.49 81.38,31.76 95.35,31.76 96.62,30.49 97.89,30.49 IC29.25 100.43,30.49 101.7,31.76 116.94,31.76 118.21,30.49 IC23.25 | v116.94,36.84 116.94,41.29 115.67,42.56 115.67,47 112.49,50.18 103.6,50.18 102.33,48.91 IC17.16
A09  (via drill 0.61)
  Top 0.254: v108.68,42.56 v106.78,44.46
  Bottom 0.254: IC22.24 80.11,27.95 81.38,29.22 96.62,29.22 97.89,27.95 IC29.24 100.43,27.95 101.7,29.22 116.94,29.22 118.21,27.95 IC23.24 120.11,28.59 121.38,28.59 121.38,33.67 120.75,34.3 108.68,34.3 v108.68,42.56 | v106.78,44.46 104.24,47 IC17.17
A10
  Top 0.254: IC17.18 106.78,47 104.24,44.46 99.79,44.46 97.25,41.92 97.25,20.97 98.52,20.97 IC29.21
  Bottom 0.254: IC22.21 80.11,20.33 81.38,21.6 85.82,21.6 87.09,20.33 97.89,20.33 IC29.21 100.43,20.33 101.7,21.6 116.94,21.6 118.21,20.33 IC23.21
A11  (via drill 0.61)
  Top 0.254: v113.76,47 113.13,46.37 111.22,46.37 109.95,47.64 IC17.19 | v115.67,36.84 115.67,26.05 118.84,26.05 IC23.23
  Bottom 0.254: IC22.23 80.11,25.41 81.38,26.68 95.35,26.68 96.62,25.41 97.89,25.41 IC29.23 100.43,25.41 101.7,26.68 116.94,26.68 118.21,25.41 IC23.23 | v113.76,47 113.76,41.92 115.03,41.92 115.67,41.29 v115.67,36.84
A12  (via drill 0.61)
  Top 0.254: IC22.2 64.87,35.57 65.5,36.21 76.93,36.21 77.57,36.84 81.38,36.84 82.65,35.57 IC29.2 85.19,35.57 87.09,37.48 v93.44,37.48
  Bottom 0.254: IC17.20 111.22,47.64 107.41,43.83 107.41,38.75 104.87,36.21 IC23.2 102.97,35.57 101.7,35.57 100.43,34.3 96.62,34.3 v93.44,37.48
A13  (via drill 0.61)
  Top 0.254: v61.69,13.98 40.74,13.98 39.47,15.25 IC19.4 | v99.16,50.81 98.52,50.18 93.44,50.18 92.81,49.54 92.81,45.1 90.27,45.1 90.27,38.75 v89,38.75
  Bottom 0.254: v61.69,13.98 64.87,13.98 73.76,22.87 73.76,32.4 78.2,32.4 IC22.26 79.47,33.67 82.65,36.84 90.9,36.84 | IC23.26 118.21,33.03 108.68,33.03 107.41,34.3 101.7,34.3 100.43,33.03 IC29.26 97.89,33.03 94.71,33.03 90.9,36.84 | v99.16,50.81 106.78,50.81 106.78,59.7 108.05,60.97 109.32,60.97 111.22,62.88 IC17.21 | 90.9,36.84 v89,38.75
A14  (via drill 0.61)
  Top 0.254: v66.14,27.95 66.77,28.59 76.93,28.59 77.57,29.22 88.36,29.22 96.62,37.48 96.62,44.46 v97.25,44.46
  Bottom 0.254: v66.14,27.95 66.14,25.41 64.87,24.14 62.33,24.14 59.79,21.6 53.44,21.6 52.17,20.33 IC28.2 | v97.25,44.46 97.25,46.37 97.89,47 97.89,52.08 101.06,52.08 106.14,57.16 106.14,61.61 107.41,61.61 108.68,62.88 IC17.22
A15  (via drill 0.61)
  Top 0.254: v74.39,38.11 76.3,38.11 77.57,39.38 80.11,39.38 82.65,36.84 85.19,36.84 89,40.65 89,41.92 EP2.3 | v102.97,56.53 96.62,56.53 v90.9,50.81
  Bottom 0.254: v74.39,38.11 71.85,35.57 71.22,35.57 71.22,22.87 64.87,16.52 53.44,16.52 52.17,17.79 IC28.3 | v102.97,56.53 102.97,59.7 106.14,62.88 IC17.23 | v90.9,50.81 90.9,50.18 90.27,49.54 90.27,44.46 89,44.46 EP2.3
CB1
  Top 0.254: R14.1 12.8,23.51 12.8,24.14 JP3.2 12.8,26.68 17.88,26.68 17.88,30.49 19.78,32.4 IC24.18
CDEF\  (via drill 0.61)
  Top 0.254: v96.62,10.17 97.89,8.9 108.05,8.9 v115.67,16.52 | IC23.22 118.84,22.24 117.57,20.97 117.57,18.43 118.84,18.43 IC23.20
  Bottom 0.254: v96.62,10.17 87.09,10.17 85.82,11.44 82.65,11.44 80.11,13.98 77.57,13.98 67.41,3.82 56.61,3.82 56.61,5.73 57.88,7 IC28.10 | v115.67,16.52 116.94,17.79 118.21,17.79 IC23.20
D0  (via drill 0.61)
  Top 0.254: IC22.11 64.87,12.71 66.14,11.44 81.38,11.44 82.65,12.71 IC29.11 | IC21.22 54.71,55.89 53.44,57.16 38.2,57.16 36.93,58.43 IC24.33 | v75.03,30.49 73.76,31.76 v66.14,31.76
  Bottom 0.254: IC23.11 102.97,12.71 101.7,11.44 87.09,11.44 85.82,12.71 85.19,12.71 IC29.11 | 72.49,53.35 59.79,53.35 57.25,55.89 IC21.22 | 72.49,53.35 75.03,53.35 75.03,58.43 77.57,60.97 80.11,60.97 80.11,64.78 80.74,65.42 84.55,65.42 85.82,64.15 IC17.31 | v75.03,30.49 75.03,22.87 64.87,12.71 IC22.11 | v66.14,31.76 66.14,40.65 68.04,40.65 72.49,45.1 72.49,53.35
D1  (via drill 0.61)
  Top 0.254: IC22.12 64.87,10.17 66.14,8.9 80.11,8.9 81.38,10.17 82.65,10.17 IC29.12 85.19,10.17 86.46,11.44 101.7,11.44 102.97,10.17 IC23.12 | v45.18,54.62 v53.44,54.62 | v89,59.7 87.73,58.43 78.84,58.43 77.57,57.16 61.06,57.16 57.25,53.35 IC21.21 | v29.31,50.81 34.39,55.89 IC24.32
  Bottom 0.254: v45.18,54.62 38.2,54.62 36.93,55.89 IC24.32 | v53.44,54.62 54.71,53.35 IC21.21 | v89,59.7 89,62.24 IC17.30 | v29.31,50.81 31.85,48.27 32.48,48.27 32.48,10.81 36.93,6.36 39.47,6.36 42.01,3.82 47.09,3.82 49.63,6.36 52.17,6.36 54.71,8.9 61.06,8.9 62.33,10.17 IC22.12
D2
  Top 0.254: 81.38,6.36 66.14,6.36 64.87,7.63 IC22.13 62.33,7.63 61.06,8.9 42.01,8.9 39.47,11.44 36.93,11.44 35.66,12.71 35.66,21.6 40.74,21.6 42.01,20.33 43.28,20.33 44.55,21.6 47.09,21.6 47.72,22.24 47.72,26.68 47.09,27.32 47.09,29.22 52.17,29.22 54.07,31.13 54.07,41.92 57.25,41.92 57.88,42.56 57.88,50.18 56.61,50.18 IC21.20 54.71,50.81 53.44,52.08 52.17,52.08 | 81.38,6.36 82.65,7.63 IC29.13 | 81.38,6.36 101.7,6.36 102.97,7.63 IC23.13 | 52.17,52.08 38.2,52.08 36.93,53.35 IC24.31 | 52.17,52.08 54.71,54.62 57.25,54.62 60.42,57.8 76.93,57.8 78.2,59.07 87.09,59.07 90.9,62.88 IC17.29
D3  (via drill 0.61)
  Top 0.254: IC21.19 54.71,48.27 53.44,49.54 38.2,49.54 36.93,50.81 IC24.30 | v38.83,66.69 36.93,64.78 34.39,64.78 33.75,64.15 33.75,57.16 36.93,57.16 37.56,56.53 37.56,54.62 34.39,54.62 33.75,53.99 33.75,51.45 35.02,51.45 IC24.30 | v29.31,13.98 36.93,6.36 64.87,6.36 65.5,5.73 76.93,5.73 77.57,5.09 IC22.15 | v29.31,48.27 31.85,50.81 34.39,50.81 IC24.30
  Bottom 0.254: 96.62,6.36 81.38,6.36 80.11,5.09 IC22.15 | 96.62,6.36 97.89,5.09 IC29.15 | 96.62,6.36 116.94,6.36 118.21,5.09 IC23.15 | v38.83,66.69 43.91,66.69 43.91,81.29 47.72,85.1 64.23,85.1 64.23,83.2 69.31,78.12 77.57,78.12 77.57,70.5 81.38,66.69 90.9,66.69 93.44,64.15 IC17.28 | v29.31,13.98 v29.31,48.27
D4  (via drill 0.61)
  Top 0.254: IC21.18 54.71,45.73 53.44,47 38.2,47 36.93,48.27 IC24.29 34.39,48.27 v30.58,48.27 | IC22.16 80.11,7.63 81.38,8.9 96.62,8.9 97.89,7.63 IC29.16 | v93.44,66.69 102.97,66.69 102.97,69.86 v114.4,69.86
  Bottom 0.254: v114.4,69.86 116.94,67.32 118.21,67.32 122.02,63.51 122.02,47 123.92,47 125.19,45.73 125.19,8.9 | 125.19,8.9 125.19,8.27 120.11,8.27 IC23.16 | IC17.27 95.98,64.15 v93.44,66.69 92.81,67.32 82.65,67.32 82.65,82.56 78.84,86.37 41.37,86.37 38.83,83.83 10.89,83.83 8.99,81.93 1.37,81.93 1.37,60.34 2,59.7 8.99,59.7 11.53,57.16 21.69,57.16 v30.58,48.27 | 125.19,8.9 101.7,8.9 100.43,7.63 IC29.16
D5  (via drill 0.61)
  Top 0.254: IC21.17 54.71,43.19 53.44,44.46 36.93,44.46 36.29,45.1 IC24.28 | v60.42,43.83 59.79,43.83 59.79,48.27 68.04,56.53 78.2,56.53 79.47,57.8 93.44,57.8 98.52,62.88 IC17.26 | v111.22,57.16 110.59,57.8 v100.43,57.8
  Bottom 0.254: IC22.17 80.11,10.17 81.38,8.9 96.62,8.9 97.89,10.17 IC29.17 100.43,10.17 101.7,10.17 102.97,11.44 116.94,11.44 118.21,10.17 IC23.17 120.11,10.81 123.92,14.62 123.92,44.46 122.65,44.46 121.38,45.73 121.38,57.16 v111.22,57.16 | v60.42,43.83 59.79,43.19 57.25,43.19 IC21.17 | v100.43,57.8 100.43,62.24 99.16,62.24 IC17.26
D6  (via drill 0.61)
  Top 0.254: IC22.18 80.11,12.71 81.38,13.98 95.35,13.98 96.62,12.71 97.89,12.71 IC29.18 | v102.97,55.26 104.24,53.99 115.03,53.99 115.67,54.62 119.48,54.62 120.75,53.35 120.75,42.56 123.92,39.38 123.92,15.89 120.75,12.71 IC23.18 | v31.21,38.75 35.02,42.56 IC24.27
  Bottom 0.254: IC24.27 36.93,43.19 38.2,41.92 53.44,41.92 54.71,40.65 IC21.16 | v102.97,55.26 101.7,55.26 101.7,62.24 IC17.25 | IC29.18 100.43,12.71 101.7,13.98 116.94,13.98 118.21,12.71 IC23.18 | v31.21,38.75 31.21,11.44 31.85,10.81 31.85,2.55 67.41,2.55 77.57,12.71 IC22.18
D7  (via drill 0.61)
  Top 0.254: v61.69,43.83 62.33,43.83 62.33,49.54 68.68,55.89 78.84,55.89 80.11,57.16 97.89,57.16 103.6,62.88 IC17.24 104.24,62.24 108.05,58.43 112.49,58.43 v112.49,55.26
  Bottom 0.254: IC22.19 80.11,15.25 81.38,13.98 96.62,13.98 97.89,15.25 IC29.19 100.43,15.25 101.7,16.52 105.51,16.52 106.78,15.25 118.21,15.25 IC23.19 120.11,15.89 123.29,19.06 123.29,41.92 121.38,41.92 120.75,42.56 120.75,52.08 115.67,52.08 v112.49,55.26 | IC24.26 36.93,40.65 38.2,39.38 53.44,39.38 54.71,38.11 IC21.15 56.61,38.75 v61.69,43.83
E  (via drill 0.61)
  Top 0.254: IC18.9 123.92,53.99 123.92,55.26 IC18.10 123.29,55.89 v120.75,58.43 | v108.05,59.7 105.51,62.24 105.51,65.42 80.74,65.42 79.47,64.15 IC17.34 | v30.58,71.13 34.39,74.94 47.72,74.94 51.53,78.75 52.17,78.75 IC2.3
  Bottom 0.254: IC21.14 54.71,35.57 53.44,36.84 36.93,36.84 36.29,37.48 IC24.25 35.02,38.75 33.12,40.65 33.12,48.91 30.58,51.45 v30.58,71.13 | 58.52,73.67 60.42,71.77 IC2.9 | 58.52,73.67 54.07,78.12 IC2.3 | 58.52,73.67 54.71,69.86 51.53,69.86 51.53,66.05 52.8,64.78 55.98,64.78 59.79,60.97 76.3,60.97 78.2,62.88 IC17.34 | v120.75,58.43 119.48,59.7 v108.05,59.7
EP
  Top 0.254: IC28.4 52.17,15.25 57.25,15.25 IC28.13
EP1\  (via drill 0.61)
  Top 0.254: v55.98,19.06 57.25,17.79 IC28.14
  Bottom 0.254: v55.98,19.06 48.99,19.06 48.99,17.16 49.63,16.52 52.17,16.52 52.8,15.89 54.71,15.89 54.71,11.44 51.53,8.27 IC28.7
FIRQ\  (via drill 0.61)
  Top 0.254: R8.1 71.22,46.37 71.22,47 IC17.4 | IC24.37 35.02,69.23 35.02,70.5 IC24.38 | v43.28,55.89 v47.09,55.89
  Bottom 0.254: v47.09,55.89 50.9,52.08 57.25,52.08 57.88,51.45 68.04,51.45 70.58,48.91 IC17.4 | v43.28,55.89 42.01,57.16 39.47,57.16 36.93,59.7 34.39,59.7 33.75,60.34 33.75,68.59 34.39,68.59 IC24.37
GND  (via drill 0.61)
  Top 0.508: JP3.1 9.62,26.05 8.35,27.32 IC26.10 8.35,28.59 13.43,33.67 13.43,48.27 14.07,48.27 IC26.19 14.7,48.91 14.07,48.91 10.26,52.72 BYP26.2 10.26,53.99 8.99,55.26 8.35,55.26 IC25.10 | 17.88,1.28 14.07,5.09 IC27.7 | 17.88,1.28 26.13,1.28 27.4,2.55 C.2 28.04,3.19 28.04,4.46 C6.2 | 17.88,1.28 10.89,1.28 5.18,7 C7.2 | C6.2 28.67,5.09 36.93,5.09 IC19.8 39.47,5.09 40.74,3.82 48.36,3.82 | C6.2 28.04,5.73 28.04,7 C4.2 28.04,8.27 28.04,9.54 C5.2 | 48.36,3.82 49.63,5.09 IC28.8 | 61.06,3.82 62.33,5.09 IC22.14 | 48.36,3.82 61.06,3.82 | 81.38,3.82 82.65,5.09 IC29.14 | 61.06,3.82 81.38,3.82 | 81.38,3.82 101.7,3.82 102.97,5.09 IC23.14 | 64.23,74.31 64.87,73.67 65.5,73.67 BYP20.2 | 64.23,74.31 62.33,76.21 IC2.11 61.69,76.85 62.96,78.12 62.96,80.02 57.25,80.02 54.71,77.48 51.53,77.48 42.64,68.59 41.37,68.59 QG1.7 40.74,67.96 40.74,66.05 | 64.23,74.31 70.58,80.66 IC20.15 71.85,81.93 73.12,83.2 82.01,83.2 83.28,81.93 IC20.10 | BYP23.2 99.79,45.73 100.43,45.73 EP-1.1 102.33,46.37 102.97,47 102.97,50.18 | BYP18.2 115.03,50.81 115.67,50.81 IC18.7 116.94,50.18 116.94,48.27 JP1.1 116.94,45.73 114.4,45.73 | 114.4,45.73 114.4,41.29 BYP29.2 | 102.97,50.18 107.41,50.18 108.05,49.54 108.05,45.73 114.4,45.73 | COM.5 109.95,71.77 114.4,71.77 COM.G2 118.21,74.31 122.02,78.12 C3.2 | 102.97,50.18 101.06,52.08 v95.35,52.08 | v47.09,60.97 42.01,60.97 IC21.1 40.74,61.61 40.74,62.88 BYP21.2 40.74,64.15 40.74,66.05 | 40.74,66.05 52.8,66.05 BYP2.2 | IC25.19 16.61,76.21 19.15,76.21 IC24.1 20.42,76.85 20.42,78.12 BYP24.2 | BYP25.2 10.26,80.66 14.07,76.85 14.7,76.85 IC25.19 | IC28.1 51.53,23.51 52.8,24.78 53.44,24.78 BYP28.2 53.44,26.05 53.44,27.95 55.34,27.95 59.79,32.4 59.79,42.56 63.6,42.56 BYP17.2 63.6,43.83 63.6,47 IC17.1
  Top 0.508: v66.77,41.92 71.85,41.92 73.12,40.65 BYP22.2 | IC25.10 6.45,55.89 5.81,55.89 CORE-IO.10 | v26.77,29.22 38.83,29.22 40.1,27.95 R13.1 40.74,27.32 40.74,26.05 BYP19.2 40.74,24.78 43.28,24.78 v43.28,21.6 | IC25.19 14.7,75.58 10.26,71.13 10.26,56.53 8.35,56.53 IC25.10
  Bottom 0.508: JP3.1 10.26,24.14 3.91,17.79 3.91,8.27 5.18,8.27 C7.2 | 69.95,67.32 66.77,64.15 IC17.39 | 69.95,67.32 74.39,67.32 75.66,68.59 C11.2 | 69.95,67.32 69.95,75.58 67.41,75.58 66.14,74.31 BYP20.2 | IC20.10 83.92,80.02 89.63,74.31 90.27,74.31 COM.G1 91.54,70.5 95.98,66.05 97.89,66.05 | 97.89,66.05 99.16,67.32 RS-232.2 | 97.89,66.05 104.87,66.05 109.32,70.5 COM.5 | v95.35,52.08 95.35,53.99 97.25,53.99 97.89,54.62 97.89,66.05 | v47.09,60.97 52.17,60.97 54.71,58.43 IC21.23 | 10.26,72.4 6.45,72.4 5.18,71.13 JP4.1 | 10.26,72.4 14.07,76.21 IC25.19 | 10.26,72.4 37.56,72.4 40.74,69.23 QG1.7 | v66.77,41.92 65.5,43.19 64.23,43.19 BYP17.2 | CORE-IO.11 3.27,53.35 5.18,55.26 CORE-IO.10 | 25.5,30.49 21.69,26.68 17.24,26.68 15.97,25.41 BYP27.2 | 25.5,30.49 25.5,47 17.88,47 16.61,48.27 IC26.19 | 25.5,30.49 v26.77,29.22 | v43.28,21.6 48.36,21.6 49.63,22.87 IC28.1
HLT\
  Top 0.254: IC17.40 63.6,64.78 63.6,65.42 R5.1
IO-E\
  Bottom 0.254: IC19.9 44.55,5.09 40.74,8.9 36.93,8.9 33.75,12.08 33.75,33.03 34.39,33.03 IC24.23
IO-F\  (via drill 0.61)
  Top 0.254: v33.75,34.3 36.93,34.3 39.47,36.84 42.01,36.84 42.64,37.48 42.64,40.02 41.37,40.02 IC21.9
  Bottom 0.254: v33.75,34.3 33.12,34.3 33.12,11.44 36.93,7.63 IC19.7
IRQ\
  Top 0.254: R7.1 38.83,45.73 39.47,45.73 IC21.7
  Bottom 0.254: IC17.3 68.04,47.64 66.77,46.37 62.33,46.37 61.69,47 43.28,47 42.01,45.73 IC21.7
N$1
  Bottom 0.254: COM.6 100.43,73.04 101.06,72.4 106.14,72.4 106.78,71.77 COM.4
N$2
  Top 0.254: QG1.8 48.36,69.23 52.17,73.04 52.8,73.04 IC2.5
  Bottom 0.254: IC2.1 52.8,83.2 51.53,81.93 51.53,74.31 52.8,74.31 IC2.5
N$3
  Bottom 0.254: IC2.10 61.69,74.31 62.96,75.58 62.96,80.66 61.69,80.66 IC2.13
N$4  (via drill 0.61)
  Top 0.254: v109.95,39.38 106.14,43.19 102.97,43.19 EP-1.2
  Bottom 0.254: v109.95,39.38 113.76,35.57 118.21,35.57 IC23.27
N$5
  Top 0.254: IC25.18 16.61,73.67 19.15,73.67 IC24.2
N$6
  Top 0.254: IC18.5 116.3,56.53 116.3,57.8 IC18.4 116.3,59.07 116.3,60.34 IC18.3
N$7
  Bottom 0.254: IC2.8 61.69,69.23 63.6,71.13 63.6,83.2 61.69,83.2 IC2.14
N$21
  Top 0.254: 116.3,68.59 121.38,68.59 C3.1 | 116.3,68.59 112.49,68.59 R1.1 | 116.3,68.59 116.3,66.69 IC18.1
N$22  (via drill 0.61)
  Top 0.254: v119.48,53.35 119.48,48.27 JP1.2 | v119.48,55.89 119.48,62.88 117.57,62.88 IC18.2
  Bottom 0.254: IC18.2 116.3,64.15 115.03,65.42 114.4,65.42 R2.1 | v119.48,53.35 v119.48,55.89
N$23  (via drill 0.61)
  Top 0.254: v28.04,48.27 31.85,52.08 v32.48,52.08 | IC21.3 40.1,55.26 40.1,53.99 IC21.4
  Bottom 0.254: v28.04,48.27 28.04,27.95 24.23,24.14 18.51,24.14 18.51,15.89 13.43,10.81 IC27.5 | v32.48,52.08 38.2,52.08 39.47,53.35 IC21.4
N$24
  Top 0.254: IC26.18 15.97,46.37 17.24,47.64 17.24,53.35 19.15,53.35 IC24.10
N$25
  Top 0.254: IC26.17 15.97,43.83 17.88,45.73 17.88,50.81 19.15,50.81 IC24.11
N$27
  Top 0.254: IC27.2 11.53,17.79 10.89,17.79 R11.A | C.1 22.96,3.19 22.96,4.46 C6.1 | IC27.6 11.53,7.63 9.62,9.54 8.35,9.54 R11.S
  Bottom 0.254: C6.1 22.96,5.73 22.32,6.36 15.34,6.36 14.07,7.63 IC27.6 | R11.A 10.26,16.52 10.26,11.44 7.72,11.44 R11.S
N$28
  Bottom 0.254: R9.1 29.94,2.55 28.67,3.82 22.32,3.82 21.05,2.55 R10.2 19.78,2.55 18.51,1.28 10.89,1.28 7.72,4.46 6.45,4.46 6.45,17.16 8.99,19.7 10.89,19.7 11.53,20.33 IC27.1
N$94
  Top 0.254: IC26.16 15.97,41.29 18.51,43.83 18.51,48.27 19.15,48.27 IC24.12
N$124
  Bottom 0.254: IC26.15 15.97,38.75 17.88,40.65 17.88,45.73 19.15,45.73 IC24.13
N$125
  Bottom 0.254: IC26.14 15.97,36.21 18.51,38.75 18.51,43.19 19.15,43.19 IC24.14
N$126
  Top 0.254: IC26.13 15.97,33.67 17.24,34.94 17.24,40.65 19.15,40.65 IC24.15
N$127
  Top 0.254: IC26.12 15.97,31.13 17.88,33.03 17.88,38.11 19.15,38.11 IC24.16
N$128
  Top 0.254: IC26.11 15.97,28.59 17.24,29.86 17.24,31.13 18.51,32.4 18.51,35.57 19.15,35.57 IC24.17
N$129
  Top 0.254: IC25.17 16.61,71.13 19.15,71.13 IC24.3
N$130
  Top 0.254: IC25.16 16.61,68.59 19.15,68.59 IC24.4
N$131
  Top 0.254: IC25.15 16.61,66.05 19.15,66.05 IC24.5
N$132
  Top 0.254: IC25.14 16.61,63.51 19.15,63.51 IC24.6
N$133
  Top 0.254: IC25.13 16.61,60.97 19.15,60.97 IC24.7
N$134
  Top 0.254: IC25.12 16.61,58.43 19.15,58.43 IC24.8
N$135
  Top 0.254: IC25.11 16.61,55.89 19.15,55.89 IC24.9
N$136
  Bottom 0.254: IC24.19 19.78,31.13 16.61,34.3 14.07,34.3 10.26,38.11 10.26,50.18 8.35,50.18 IC26.1
N$137
  Bottom 0.254: IC25.1 8.99,78.75 10.26,80.02 16.61,80.02 18.51,78.12 18.51,74.94 33.12,74.94 34.39,73.67 IC24.39
N$138  (via drill 0.61)
  Top 0.254: v24.23,31.76 24.23,56.53 28.04,56.53 29.31,57.8 29.31,76.21 34.39,76.21 IC24.40
  Bottom 0.254: v24.23,31.76 21.69,29.22 11.53,29.22 11.53,22.24 12.16,21.6 14.7,21.6 14.7,14.62 14.07,13.98 10.89,13.98 10.89,9.54 11.53,8.9 17.88,8.9 19.15,7.63 IC27.9
N$140
  Top 0.254: IC27.8 21.05,5.73 22.32,7 22.96,7 C4.1 23.59,7.63 25.5,9.54 R4.1
  Bottom 0.254: IC27.12 21.05,14.62 24.86,10.81 25.5,10.81 R4.1
N$141
  Top 0.254: IC27.13 21.69,17.79 22.32,17.79 R3.1 23.59,17.79 24.86,17.79 R4.2
N$142
  Top 0.254: IC27.11 21.69,12.71 24.23,15.25 27.4,15.25 C5.1
N$143
  Top 0.254: R10.1 12.16,2.55 10.89,3.82 10.26,3.82 R11.E
N$145
  Top 0.254: COM.7 103.6,73.67 104.87,73.67 COM.8
N$147  (via drill 0.61)
  Top 0.254: v51.53,63.51 52.17,64.15 59.15,64.15 67.41,72.4 67.41,75.58 93.44,75.58 v94.08,74.94 | IC18.12 123.92,61.61 123.92,62.88 IC18.13
  Bottom 0.254: v51.53,63.51 50.26,62.24 45.82,62.24 45.82,55.89 46.45,55.26 46.45,54.62 45.18,53.35 44.55,53.35 42.01,50.81 IC21.5 | v94.08,74.94 96.62,77.48 116.3,77.48 123.29,70.5 123.29,67.32 122.65,66.69 122.65,64.15 123.92,64.15 IC18.13
N$148
  Bottom 0.254: LED1.K 123.29,48.91 123.29,49.54 122.65,50.18 122.65,58.43 123.29,58.43 IC18.11
N$149
  Top 0.254: R12.1 122.02,43.83 123.29,45.1 LED1.A
N$150  (via drill 0.61)
  Top 0.254: R13.2 48.99,27.95 49.63,27.95 JP2.1 51.53,28.59 54.07,28.59 57.88,32.4 58.52,32.4 58.52,48.27 61.06,50.81 v61.06,55.89
  Bottom 0.254: v61.06,55.89 56.61,60.34 IC21.24
N$151  (via drill 0.61)
  Top 0.254: v72.49,19.06 61.06,19.06 59.79,20.33 IC28.15 | v90.27,24.14 95.35,19.06 114.4,19.06 117.57,15.89 117.57,11.44 120.75,11.44 124.56,15.25 124.56,50.18 IC18.8
  Bottom 0.254: v72.49,19.06 77.57,24.14 v90.27,24.14
N$153
  Top 0.254: IC20.7 84.55,73.04 85.82,73.04 IC20.8
N$154
  Top 0.254: C7.1 5.81,12.71 8.35,15.25 11.53,15.25 IC27.3
N$155
  Top 0.254: C9.2 80.74,71.13 79.47,72.4 78.84,72.4 IC20.5
N$156
  Top 0.254: C9.1 76.3,71.77 76.3,72.4 IC20.4
N$157
  Top 0.254: C8.2 73.76,69.23 75.03,70.5 75.03,72.4 73.76,72.4 IC20.3
N$158
  Top 0.254: C8.1 68.68,69.23 69.95,70.5 69.95,72.4 68.68,72.4 IC20.1
N$159
  Top 0.254: C11.1 81.38,69.23 82.65,70.5 82.65,72.4 81.38,72.4 IC20.6
N$160
  Top 0.254: C10.2 73.12,71.13 71.85,72.4 71.22,72.4 IC20.2
NMI\
  Top 0.254: R6.1 68.04,45.73 66.77,47 66.14,47 IC17.2
P1
  Top 0.254: IC29.1 84.55,38.75 86.46,40.65 86.46,41.92 EP2.2
P27  (via drill 0.61)
  Top 0.254: v94.08,39.38 91.54,41.92 EP2.4
  Bottom 0.254: v94.08,39.38 97.89,35.57 IC29.27
PIA-A0
  Bottom 0.254: IC25.2 6.45,76.21 5.18,74.94 2.64,74.94 2,74.31 2,66.69 2.64,66.69 CORE-IO.1
PIA-A1
  Top 0.254: IC25.3 7.08,73.04 5.81,71.77 5.81,66.69 5.18,66.69 CORE-IO.2
PIA-A2
  Bottom 0.254: IC25.4 7.08,70.5 3.91,67.32 3.91,65.42 2.64,64.15 CORE-IO.3
PIA-A3
  Top 0.254: IC25.5 8.35,67.96 9.62,66.69 9.62,64.78 5.81,64.78 5.18,64.15 CORE-IO.4
PIA-A4
  Bottom 0.254: IC25.6 8.35,65.42 9.62,64.15 9.62,62.24 4.54,62.24 3.27,60.97 CORE-IO.5
PIA-A5
  Top 0.254: IC25.7 7.08,62.88 5.81,61.61 5.18,61.61 CORE-IO.6
PIA-A6
  Top 0.254: IC25.8 7.08,60.34 6.45,59.7 4.54,59.7 3.27,58.43 CORE-IO.7
PIA-A7
  Top 0.254: IC25.9 6.45,58.43 5.81,58.43 CORE-IO.8
PIA-B0
  Bottom 0.254: IC26.2 7.08,48.91 6.45,49.54 4.54,49.54 3.27,50.81 CORE-IO.13
PIA-B1
  Top 0.254: IC26.3 8.35,46.37 9.62,47.64 9.62,49.54 5.81,49.54 5.18,50.18 CORE-IO.14
PIA-B2
  Top 0.254: IC26.4 7.08,43.83 6.45,44.46 4.54,44.46 3.91,45.1 3.91,47.64 2.64,47.64 CORE-IO.15
PIA-B3
  Bottom 0.254: IC26.5 8.35,41.29 9.62,42.56 9.62,47 5.81,47 5.18,47.64 CORE-IO.16
PIA-B4
  Top 0.254: IC26.6 7.08,38.75 3.91,41.92 3.91,43.83 2.64,45.1 CORE-IO.17
PIA-B5
  Bottom 0.254: IC26.7 7.08,36.21 3.91,39.38 3.91,45.73 4.54,45.73 CORE-IO.18
PIA-B6
  Top 0.254: IC26.8 7.08,33.67 2.64,38.11 2.64,42.56 CORE-IO.19
PIA-B7
  Top 0.254: IC26.9 8.35,31.13 9.62,32.4 9.62,41.92 5.81,41.92 5.18,42.56 CORE-IO.20
Q  (via drill 0.61)
  Top 0.254: v56.61,70.5 56.61,74.31 60.42,78.12 IC2.12
  Bottom 0.254: IC17.35 75.66,62.88 74.39,61.61 60.42,61.61 54.07,67.96 IC2.7 54.71,68.59 v56.61,70.5
R/W\  (via drill 0.61)
  Top 0.254: v61.06,33.03 62.33,34.3 65.5,34.3 66.77,35.57 77.57,35.57 IC22.27
  Bottom 0.254: IC24.21 36.93,27.95 40.74,31.76 53.44,31.76 54.71,33.03 IC21.13 57.25,33.03 v61.06,33.03 | IC22.27 78.2,36.21 76.93,37.48 76.93,41.92 82.01,41.92 82.65,41.29 93.44,41.29 94.08,41.92 EP2.5 94.08,44.46 92.81,44.46 92.81,53.35 83.92,62.24 IC17.32
RST\  (via drill 0.61)
  Top 0.254: v44.55,62.24 62.33,62.24 62.96,61.61 69.31,61.61 70.58,62.88 IC17.37 | v96.62,55.26 99.79,55.26 101.7,53.35 115.67,53.35 IC18.6
  Bottom 0.254: v44.55,62.24 38.2,62.24 36.93,60.97 IC24.34 | v96.62,55.26 90.27,61.61 90.27,66.05 73.76,66.05 71.85,64.15 IC17.37
RX  (via drill 0.61)
  Top 0.254: v44.55,59.07 45.18,59.7 75.03,59.7 77.57,62.24 77.57,71.13 v78.84,71.13
  Bottom 0.254: v44.55,59.07 42.64,59.07 42.01,58.43 IC21.2 | v78.84,71.13 80.11,72.4 80.11,80.02 78.84,80.02 IC20.12
RXD
  Top 0.254: 96.62,72.4 96.62,69.86 RS-232.3 | 96.62,72.4 96.62,73.67 94.08,76.21 80.11,76.21 76.3,80.02 IC20.13 | 96.62,72.4 102.33,72.4 103.6,71.13 COM.3
TX
  Bottom 0.254: IC21.6 39.47,48.27 38.2,49.54 33.75,49.54 31.21,52.08 31.21,69.86 37.56,69.86 40.1,67.32 41.37,67.32 43.28,69.23 43.28,85.74 76.93,85.74 80.74,81.93 IC20.11
TXD  (via drill 0.61)
  Top 0.254: v78.84,78.75 80.74,76.85 94.71,76.85 v97.89,73.67 | RS-232.1 101.7,69.86 101.7,70.5 COM.2
  Bottom 0.254: v78.84,78.75 76.3,78.75 74.39,80.66 IC20.14 | v97.89,73.67 99.16,72.4 99.79,72.4 100.43,71.77 101.06,71.77 COM.2
VCC  (via drill 0.61)
  Top 0.508: EP2.1 83.28,42.56 81.38,40.65 79.47,40.65 BYP22.1 | IC23.28 119.48,38.75 119.48,40.02 BYP29.1 | R12.2 122.02,36.21 120.75,37.48 120.11,37.48 IC23.28 | IC29.28 99.16,38.75 99.16,40.02 BYP23.1 99.79,40.65 100.43,40.65 EP-1.3 102.33,40.02 103.6,38.75 IC23.1 105.51,38.11 118.21,38.11 IC23.28 | 15.34,11.44 16.61,10.17 19.15,10.17 IC27.10 21.69,10.17 22.32,10.17 R3.2 | 15.34,11.44 14.07,12.71 IC27.4 | 15.34,11.44 18.51,11.44 | 18.51,11.44 28.67,11.44 29.94,10.17 R9.2 | 18.51,20.97 19.15,20.33 IC27.14 20.42,20.97 20.42,24.78 BYP27.1 20.42,26.05 20.42,27.32 IC24.20 21.69,27.95 24.23,30.49 34.39,30.49 IC24.22 36.93,30.49 39.47,33.03 IC21.12 42.01,33.03 45.82,33.03 | 18.51,20.97 17.88,21.6 7.08,21.6 5.81,22.87 R14.2 | 18.51,11.44 18.51,20.97 | IC17.7 78.84,47 78.84,46.37 R8.2 78.2,45.73 75.66,43.19 69.31,43.19 BYP17.1 68.04,43.19 65.5,43.19 65.5,41.29 69.95,36.84 76.3,36.84 77.57,38.11 IC22.28 | IC24.24 36.29,36.21 37.56,37.48 38.2,37.48 R7.2 | IC21.10 39.47,38.11 38.83,38.11 R7.2 | IC21.8 40.1,42.56 38.2,40.65 38.2,38.75 R7.2 | IC28.16 58.52,23.51 58.52,24.78 BYP28.1 | IC19.16 45.82,23.51 45.82,24.78 BYP19.1 45.82,26.05 45.82,33.03 | 45.82,33.03 47.09,33.03 49.63,30.49 JP2.2 | IC26.20 15.34,51.45 15.34,52.72 BYP26.1 | CORE-IO.12 4.54,53.35 2.64,55.26 CORE-IO.9 2.64,56.53 1.37,57.8 1.37,73.67 2.64,73.67 JP4.2 | IC25.20 15.34,79.39 15.34,80.66 BYP25.1 15.97,81.29 22.32,81.29 24.86,78.75 BYP24.1 26.13,78.75 29.94,82.56 50.26,82.56 | R1.2 104.24,67.96 106.14,66.05 R2.2 107.41,66.05 111.86,66.05 113.13,64.78 114.4,64.78 | 114.4,64.78 v114.4,58.43 114.4,56.53 BYP18.1
  Top 0.508: 114.4,64.78 122.02,64.78 123.29,66.05 IC18.14 123.92,66.69 123.92,81.93 88.36,81.93 85.82,84.47 71.85,84.47 69.31,81.93 IC20.16 68.04,81.93 67.41,82.56 50.26,82.56 | 50.26,82.56 51.53,81.29 52.17,81.29 IC2.2 | 50.26,82.56 48.99,83.83 QG1.14 | 66.77,68.59 68.68,70.5 C10.1 | 66.77,68.59 BYP20.1 66.77,68.59 | 66.77,68.59 68.04,67.32 69.31,67.32 70.58,66.05 R5.2 | BYP21.1 46.45,63.51 47.72,64.78 56.61,64.78 57.88,66.05 BYP2.1 58.52,66.69 57.88,66.69 54.07,70.5 IC2.6 54.07,71.77 55.34,71.77 55.34,74.31 54.07,75.58 IC2.4 | v115.03,48.91 114.4,49.54 113.76,49.54 v111.86,51.45
  Bottom 0.508: IC22.28 78.84,38.75 78.84,40.02 BYP22.1 79.47,40.65 98.52,40.65 BYP23.1 | BYP17.1 68.04,43.19 66.77,44.46 62.96,44.46 61.69,45.73 R6.2 60.42,45.73 59.15,44.46 43.28,44.46 42.01,43.19 IC21.8 | BYP28.1 57.88,25.41 52.8,30.49 52.17,30.49 JP2.2 | IC24.24 36.93,35.57 39.47,33.03 IC21.12 | IC26.20 14.07,50.81 12.8,52.08 7.08,52.08 5.81,53.35 CORE-IO.12 | JP4.2 5.18,73.67 6.45,74.94 10.26,74.94 14.07,78.75 IC25.20 | BYP20.1 65.5,68.59 64.23,67.32 60.42,67.32 59.15,66.05 BYP2.1 | QG1.14 48.36,83.2 48.36,71.77 52.8,71.77 IC2.6 | v115.03,48.91 115.67,49.54 118.21,49.54 118.21,45.1 118.84,44.46 119.48,44.46 119.48,41.29 BYP29.1 | v111.86,51.45 111.86,53.99 109.95,55.89 109.95,58.43 v114.4,58.43

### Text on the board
Top: Component Side
Bottom: PA8PDP/VRS | Solder side
tPlace: 1 | F09 | 2,54 | 6 | 9 | 1 | 5 | 1 | + | 1 | 1 | 20 | 27256 | 62256 | 1 | 3 | 1 | 2 | 3 | RealConsole CORE - Rev.1
tNames: IC2 | QG1 | IC25 | BYP25 | IC24 | BYP24 | IC20 | C9 | JP4 | C8 | BYP20 | C3 | R5 | RS-232 | R1 | IC18 | COM | R2 | IC21 | BYP18 | IC26 | BYP26 | IC17 | LED1 | R8 | R7 | R6 | BYP17 | R12 | BYP23 | IC22 | BYP22 | BYP29 | R13 | IC19 | IC28 | BYP27 | R14 | IC27 | R3 | R4 | R10 | R9
tValues: .01uf | 4Mhz | 74LS73N | .01uf | 74LS245N | MAX232 | + | 22uf | POWER | 6821 | 10K | - | .01uf | 0.1uf | 10K | 0.1uf | 3.3K | 74LS132N | 6850 | .01uf | .01uf | 6809E | 74LS245N | 3.3K | .01uf | 3.3K | 3.3K | LO/27256 | .01uf | .01uf | HI/27128 | 270 | .01uf | 6264A | .01uf | 1K | 3.3K | 74LS138N | 74LS139N | LM556N | 100K | 100K | 3.3K | 10K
